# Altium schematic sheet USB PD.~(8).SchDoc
size A3; SheetNumber: 5; SheetTotal: 5
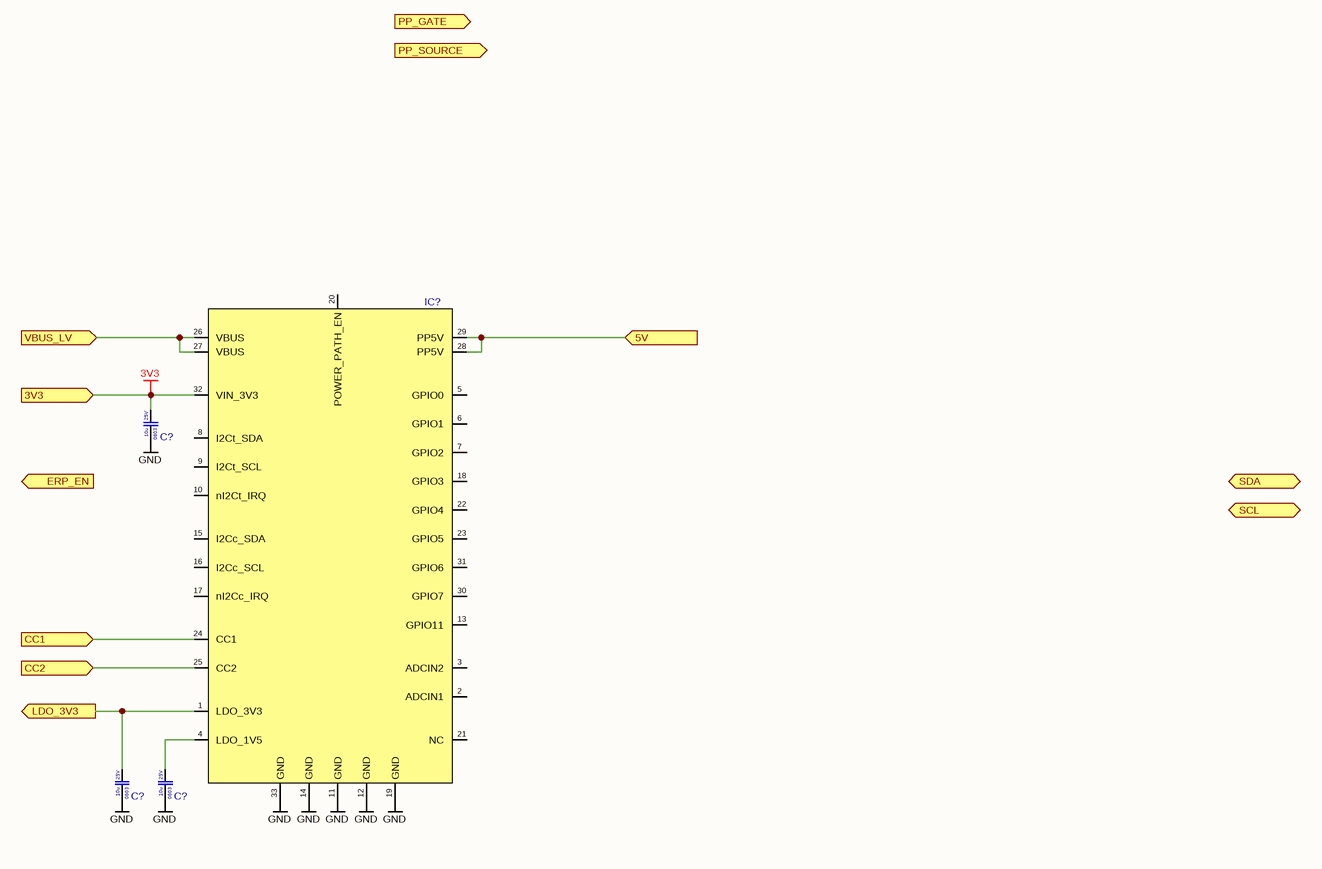
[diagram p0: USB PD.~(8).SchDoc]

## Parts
(Parts that share a designator on the sheet are numbered #1, #2 ... from top to bottom, then left to right.)
C?#1  Voltage Rating: 25V  Case Code (Imperial): 0603  Capacitance: 10u  [CAP 0603]  (hidden comment: CL10A106MA8NRNC)
C?#2  Voltage Rating: 25V  Case Code (Imperial): 0603  Capacitance: 10u  [CAP 0603]  (hidden comment: CL10A106MA8NRNC)
C?#3  Voltage Rating: 25V  Case Code (Imperial): 0603  Capacitance: 10u  [CAP 0603]  (hidden comment: CL10A106MA8NRNC)
IC?  TPS26750SRSMR  [VQFN (32) 4x4]  (value not drawn)

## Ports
3V3 (in, see Arhitecture[4B], Power distribution[5D]), 5V (in, see Arhitecture[4B], Power distribution[5C]), CC1 (in, see Arhitecture[3B]), CC2 (in, see Arhitecture[3B]), ERP_EN (in, see Arhitecture[3B]), LDO_3V3 (out, see Arhitecture[3B]), PP_GATE (out, see Arhitecture[4B]), PP_SOURCE (out, see Arhitecture[4B]), SCL (bidir, see Arhitecture[4B], Charger[3C]), SDA (bidir, see Arhitecture[4B], Charger[3C]), VBUS_LV (in, see Arhitecture[3B])

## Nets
3V3: C?#1.2 IC?.32(VIN_3V3) ; port 3V3
GND: C?#1.1 C?#2.1 C?#3.1 IC?.11(GND) IC?.12(GND) IC?.14(GND) IC?.19(GND) IC?.33(GND)
5V: IC?.28(PP5V) IC?.29(PP5V) ; port 5V
CC1: IC?.24(CC1) ; port CC1
CC2: IC?.25(CC2) ; port CC2
LDO_3V3: C?#2.2 IC?.1(LDO_3V3) ; port LDO_3V3
VBUS_LV: IC?.26(VBUS) IC?.27(VBUS) ; port VBUS_LV
NetC?#3_2: C?#3.2 IC?.4(LDO_1V5)

Not connected (* = marked no-connect by the designer): IC? 2(ADCIN1) 3(ADCIN2) 5(GPIO0) 6(GPIO1) 7(GPIO2) 8(I2Ct_SDA) 9(I2Ct_SCL) 10(nI2Ct_IRQ) 13(GPIO11) 15(I2Cc_SDA) 16(I2Cc_SCL) 17(nI2Cc_IRQ) 18(GPIO3) 20(POWER_PATH_EN) 21(NC) 22(GPIO4) 23(GPIO5) 30(GPIO7) 31(GPIO6)

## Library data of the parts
C?#1-C?#3 = CL10A106MA8NRNC: Cap 10uF 25V 0603 X5R; Manufacturer: Samsung
IC? = TPS26750SRSMR: USB PD IC EPR 240W; Manufacturer: Texas Instruments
